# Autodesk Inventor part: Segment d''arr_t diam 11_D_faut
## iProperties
Created: 2011-10
Part Number: Segment d''arr_t diam 11_D_faut
Document SubType Name: Modeling
Designer: Bruno
Author: Bruno
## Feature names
1. Base1
